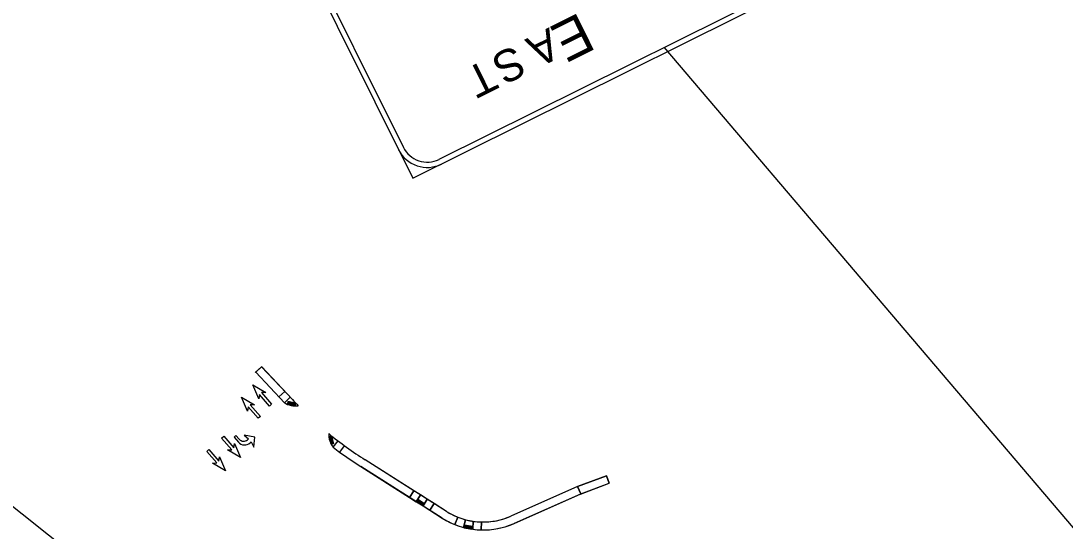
# Model space of a CAD drawing. Extents: x -5665 to 1997148, y 4 to 812485.
# Drawn here: x 1970356 to 1971011, y 803627 to 803946 of the extents above; entities that cross this region are included whole.
import ezdxf

# ---------------------------------------------------------------- set-up
doc = ezdxf.new("R2010")
doc.units = 0
for name, color, linetype in [('RD_EX_Bldg_Foundation', 7, 'Continuous'), ('RD_PD_SW', 7, 'Continuous'), ('RD_SHT_TX', 7, 'Continuous')]:
    doc.layers.add(name, color=color, linetype=linetype)

msp = doc.modelspace()

# ---------------------------------------------------------------- linework, layer by layer
at = {"layer": 'RD_EX_Bldg_Foundation'}
for p, q in [((1970505.11, 803709.66), (1970501.35, 803718.35)), ((1970501.35, 803718.35), (1970509.52, 803713.56)), ((1970498.06, 803701.97), (1970494.3, 803710.66)), ((1970494.3, 803710.66), (1970502.47, 803705.86)), ((1970505.53, 803712.27), (1970505.11, 803709.66)), ((1970511.89, 803705.08), (1970505.53, 803712.27)), ((1970509.52, 803713.56), (1970506.88, 803713.47)), ((1970506.88, 803713.47), (1970513.24, 803706.27)), ((1970498.48, 803704.58), (1970498.06, 803701.97)), ((1970504.84, 803697.39), (1970498.48, 803704.58)), ((1970502.47, 803705.86), (1970499.83, 803705.77)), ((1970499.83, 803705.77), (1970506.19, 803698.58)), ((1970513.24, 803706.27), (1970511.89, 803705.08)), ((1970506.19, 803698.58), (1970504.84, 803697.39)), ((1970481.9, 803684.94), (1970483.24, 803686.13)), ((1970488.25, 803677.74), (1970481.9, 803684.94)), ((1970483.24, 803686.13), (1970489.6, 803678.94)), ((1970490.87, 803686.65), (1970489.66, 803685.57)), ((1970490.87, 803686.65), (1970489.66, 803685.57)), ((1970489.66, 803685.57), (1970492.37, 803682.5)), ((1970489.66, 803685.57), (1970492.37, 803682.5)), ((1970492.94, 803684.3), (1970490.87, 803686.65)), ((1970490.87, 803686.65), (1970490.87, 803686.65)), ((1970492.94, 803684.3), (1970490.87, 803686.65)), ((1970490.87, 803686.65), (1970490.87, 803686.65)), ((1970502.74, 803685.51), (1970495.94, 803686.94)), ((1970495.94, 803686.94), (1970498.77, 803684.54)), ((1970502.74, 803685.51), (1970495.94, 803686.94)), ((1970495.94, 803686.94), (1970498.77, 803684.54)), ((1970498.77, 803684.54), (1970498.04, 803683.9)), ((1970498.77, 803684.54), (1970498.04, 803683.9)), ((1970502.12, 803679.28), (1970502.74, 803685.51)), ((1970502.12, 803679.28), (1970502.74, 803685.51)), ((1970472.51, 803676.64), (1970473.86, 803677.84)), ((1970478.87, 803669.45), (1970472.51, 803676.64)), ((1970473.86, 803677.84), (1970480.22, 803670.64)), ((1970485.61, 803677.65), (1970488.25, 803677.74)), ((1970493.78, 803672.86), (1970485.61, 803677.65)), ((1970489.6, 803678.94), (1970490.02, 803681.55)), ((1970490.02, 803681.55), (1970493.78, 803672.86)), ((1970499.76, 803681.96), (1970500.49, 803682.6)), ((1970499.76, 803681.96), (1970500.49, 803682.6)), ((1970500.49, 803682.6), (1970502.12, 803679.28)), ((1970500.49, 803682.6), (1970502.12, 803679.28)), ((1970480.22, 803670.64), (1970480.63, 803673.25)), ((1970480.63, 803673.25), (1970484.39, 803664.56)), ((1970476.23, 803669.36), (1970478.87, 803669.45)), ((1970484.39, 803664.56), (1970476.23, 803669.36))]:
    msp.add_line(p, q, dxfattribs=at)
for centre, radius, start, end in [((1970495.69, 803686.57), 3.56, 219.68142, 311.44424), ((1970495.69, 803686.57), 3.56, 219.68142, 311.44424), ((1970496.34, 803686), 5.29, 221.406, 310.24855), ((1970496.34, 803686), 5.29, 221.406, 310.24855)]:
    msp.add_arc(centre, radius, start, end, dxfattribs=at)
at = {"layer": 'RD_PD_SW'}
for p, q in [((1970506.97, 803729.75), (1970502.95, 803726)), ((1970506.97, 803729.75), (1970503.3, 803726.36)), ((1970506.95, 803729.78), (1970526.22, 803709.16)), ((1970526.22, 803709.16), (1970506.97, 803729.75)), ((1970503.29, 803726.36), (1970521.24, 803707.17)), ((1970503.3, 803726.36), (1970521.24, 803707.17)), ((1970517.82, 803710.82), (1970521.48, 803714.23)), ((1970521.24, 803707.17), (1970524.89, 803710.58)), ((1970551.82, 803679.24), (1970554.86, 803683.22)), ((1970555.91, 803676.19), (1970558.87, 803680.22)), ((1970622.8, 803639.13), (1970571.81, 803671.41)), ((1970602.35, 803652.07), (1970571.81, 803671.41)), ((1970620.13, 803634.9), (1970569.13, 803667.18)), ((1970569.13, 803667.18), (1970599.68, 803647.85)), ((1970704.98, 803654.59), (1970723.17, 803661.36)), ((1970723.17, 803661.36), (1970704.98, 803654.59)), ((1970706.86, 803649.96), (1970724.91, 803656.68)), ((1970707, 803650.01), (1970724.91, 803656.68)), ((1970723.17, 803661.36), (1970724.91, 803656.68)), ((1970724.91, 803656.68), (1970723.17, 803661.36)), ((1970602.35, 803652.07), (1970599.68, 803647.85)), ((1970599.68, 803647.85), (1970602.35, 803652.07)), ((1970599.68, 803647.85), (1970602.35, 803652.07)), ((1970606.58, 803649.4), (1970602.35, 803652.07)), ((1970704.98, 803654.59), (1970663.17, 803636.13)), ((1970704.98, 803654.59), (1970663.17, 803636.13)), ((1970665.19, 803631.55), (1970707, 803650.02)), ((1970706.86, 803649.96), (1970665.19, 803631.55)), ((1970707, 803650.02), (1970704.98, 803654.59)), ((1970704.98, 803654.59), (1970707, 803650.02)), ((1970599.68, 803647.85), (1970603.91, 803645.17)), ((1970603.91, 803645.17), (1970606.58, 803649.4)), ((1970606.58, 803649.4), (1970603.91, 803645.17)), ((1970603.91, 803645.17), (1970606.58, 803649.4)), ((1970603.91, 803645.17), (1970608.13, 803642.5)), ((1970610.8, 803646.72), (1970606.58, 803649.4)), ((1970610.8, 803646.72), (1970608.13, 803642.5)), ((1970608.13, 803642.5), (1970610.8, 803646.72)), ((1970608.13, 803642.5), (1970610.8, 803646.72)), ((1970615.03, 803644.05), (1970610.8, 803646.72)), ((1970612.35, 803639.82), (1970615.03, 803644.05)), ((1970615.03, 803644.05), (1970612.35, 803639.82)), ((1970612.35, 803639.82), (1970615.03, 803644.05)), ((1970622.8, 803639.13), (1970615.03, 803644.05)), ((1970608.13, 803642.5), (1970612.35, 803639.82)), ((1970612.35, 803639.82), (1970620.13, 803634.9)), ((1970628.16, 803630.82), (1970630, 803635.47)), ((1970630, 803635.47), (1970628.16, 803630.82)), ((1970628.16, 803630.82), (1970630, 803635.47)), ((1970633.52, 803629.06), (1970634.8, 803633.89)), ((1970634.8, 803633.89), (1970633.52, 803629.06)), ((1970634.8, 803633.89), (1970633.52, 803629.06)), ((1970639.39, 803627.89), (1970639.65, 803632.9)), ((1970639.65, 803632.9), (1970639.39, 803627.89)), ((1970639.65, 803632.9), (1970639.39, 803627.89)), ((1970644.61, 803627.48), (1970644.73, 803632.47)), ((1970644.73, 803632.47), (1970644.61, 803627.48)), ((1970644.61, 803627.48), (1970644.73, 803632.47))]:
    msp.add_line(p, q, dxfattribs=at)
for points in [[(1970528.29, 803706.97), (1970523.39, 803707.87), (1970523.1, 803706.29), (1970528.01, 803705.39)], [(1970550.83, 803686.33), (1970552.09, 803681.51), (1970550.55, 803681.11), (1970549.29, 803685.93)], [(1970609.02, 803643.89), (1970604.8, 803646.53), (1970603.95, 803645.18), (1970608.18, 803642.53)], [(1970639.12, 803629.55), (1970634.22, 803630.45), (1970633.93, 803628.88), (1970638.83, 803627.98)]]:
    msp.add_lwpolyline(points, close=True, dxfattribs=at)
msp.add_lwpolyline([(1970707, 803650.02), (1970707, 803650.01)], dxfattribs=at)
for centre, radius in [((1970523.45, 803706.53), 0.146), ((1970523.45, 803706.53), 0.073), ((1970523.54, 803707.02), 0.146), ((1970523.54, 803707.02), 0.073), ((1970523.64, 803707.52), 0.146), ((1970523.64, 803707.52), 0.073), ((1970523.85, 803706.46), 0.146), ((1970523.85, 803706.46), 0.073), ((1970523.94, 803706.95), 0.146), ((1970523.94, 803706.95), 0.073), ((1970524.03, 803707.45), 0.146), ((1970524.03, 803707.45), 0.073), ((1970524.24, 803706.38), 0.146), ((1970524.24, 803706.38), 0.073), ((1970524.33, 803706.87), 0.146), ((1970524.33, 803706.87), 0.073), ((1970524.42, 803707.38), 0.146), ((1970524.42, 803707.38), 0.073), ((1970524.63, 803706.31), 0.146), ((1970524.63, 803706.31), 0.073), ((1970524.72, 803706.8), 0.146), ((1970524.72, 803706.8), 0.073), ((1970524.82, 803707.3), 0.146), ((1970524.82, 803707.3), 0.073), ((1970525.03, 803706.24), 0.146), ((1970525.03, 803706.24), 0.073), ((1970525.12, 803706.73), 0.146), ((1970525.12, 803706.73), 0.073), ((1970525.21, 803707.23), 0.146), ((1970525.21, 803707.23), 0.073), ((1970525.42, 803706.17), 0.146), ((1970525.42, 803706.17), 0.073), ((1970525.51, 803706.66), 0.146), ((1970525.51, 803706.66), 0.073), ((1970525.6, 803707.16), 0.146), ((1970525.6, 803707.16), 0.073), ((1970525.81, 803706.1), 0.146), ((1970525.81, 803706.1), 0.073), ((1970525.9, 803706.59), 0.146), ((1970525.9, 803706.59), 0.073), ((1970526, 803707.09), 0.146), ((1970526, 803707.09), 0.073), ((1970526.21, 803706.02), 0.146), ((1970526.21, 803706.02), 0.073), ((1970526.3, 803706.51), 0.146), ((1970526.3, 803706.51), 0.073), ((1970526.39, 803707.01), 0.146), ((1970526.39, 803707.01), 0.073), ((1970526.6, 803705.95), 0.146), ((1970526.6, 803705.95), 0.073), ((1970526.69, 803706.44), 0.146), ((1970526.69, 803706.44), 0.073), ((1970526.78, 803706.94), 0.146), ((1970526.78, 803706.94), 0.073), ((1970527, 803705.88), 0.146), ((1970527, 803705.88), 0.073), ((1970527.09, 803706.37), 0.146), ((1970527.09, 803706.37), 0.073), ((1970527.18, 803706.87), 0.146), ((1970527.18, 803706.87), 0.073), ((1970527.39, 803705.81), 0.146), ((1970527.39, 803705.81), 0.073), ((1970527.48, 803706.3), 0.146), ((1970527.48, 803706.3), 0.073), ((1970527.57, 803706.8), 0.146), ((1970527.57, 803706.8), 0.073), ((1970527.78, 803705.73), 0.146), ((1970527.78, 803705.73), 0.073), ((1970527.87, 803706.23), 0.146), ((1970527.87, 803706.23), 0.073), ((1970527.96, 803706.73), 0.146), ((1970527.96, 803706.73), 0.073), ((1970549.64, 803685.73), 0.146), ((1970549.64, 803685.73), 0.073), ((1970549.74, 803685.34), 0.146), ((1970549.74, 803685.34), 0.073), ((1970549.84, 803684.96), 0.146), ((1970549.84, 803684.96), 0.073), ((1970549.95, 803684.57), 0.146), ((1970549.95, 803684.57), 0.073), ((1970550.05, 803684.18), 0.146), ((1970550.05, 803684.18), 0.073), ((1970550.13, 803685.86), 0.146), ((1970550.15, 803683.8), 0.146), ((1970550.13, 803685.86), 0.073), ((1970550.23, 803685.47), 0.146), ((1970550.15, 803683.8), 0.073), ((1970550.25, 803683.41), 0.146), ((1970550.23, 803685.47), 0.073), ((1970550.33, 803685.08), 0.146), ((1970550.25, 803683.41), 0.073), ((1970550.35, 803683.02), 0.146), ((1970550.33, 803685.08), 0.073), ((1970550.43, 803684.7), 0.146), ((1970550.35, 803683.02), 0.073), ((1970550.45, 803682.64), 0.146), ((1970550.43, 803684.7), 0.073), ((1970550.53, 803684.31), 0.146), ((1970550.45, 803682.64), 0.073), ((1970550.53, 803684.31), 0.073), ((1970550.62, 803685.99), 0.146), ((1970550.63, 803683.92), 0.146), ((1970550.62, 803685.99), 0.073), ((1970550.63, 803683.92), 0.073), ((1970550.72, 803685.6), 0.146), ((1970550.73, 803683.54), 0.146), ((1970550.72, 803685.6), 0.073), ((1970550.73, 803683.54), 0.073), ((1970550.82, 803685.21), 0.146), ((1970550.83, 803683.15), 0.146), ((1970550.82, 803685.21), 0.073), ((1970550.83, 803683.15), 0.073), ((1970550.92, 803684.83), 0.146), ((1970550.93, 803682.76), 0.146), ((1970550.92, 803684.83), 0.073), ((1970550.93, 803682.76), 0.073), ((1970551.02, 803684.44), 0.146), ((1970551.02, 803684.44), 0.073), ((1970551.12, 803684.05), 0.146), ((1970551.12, 803684.05), 0.073), ((1970551.22, 803683.66), 0.146), ((1970551.22, 803683.66), 0.073), ((1970551.33, 803683.28), 0.146), ((1970551.33, 803683.28), 0.073), ((1970551.43, 803682.89), 0.146), ((1970551.43, 803682.89), 0.073), ((1970551.53, 803682.5), 0.146), ((1970550.55, 803682.25), 0.146), ((1970550.55, 803682.25), 0.073), ((1970550.65, 803681.86), 0.146), ((1970550.65, 803681.86), 0.073), ((1970550.76, 803681.47), 0.146), ((1970550.76, 803681.47), 0.073), ((1970551.04, 803682.37), 0.146), ((1970551.04, 803682.37), 0.073), ((1970551.14, 803681.99), 0.146), ((1970551.14, 803681.99), 0.073), ((1970551.24, 803681.6), 0.146), ((1970551.24, 803681.6), 0.073), ((1970551.53, 803682.5), 0.073), ((1970551.63, 803682.12), 0.146), ((1970551.63, 803682.12), 0.073), ((1970551.73, 803681.73), 0.146), ((1970551.73, 803681.73), 0.073), ((1970604.36, 803645.27), 0.146), ((1970604.36, 803645.27), 0.073), ((1970604.63, 803645.69), 0.146), ((1970604.63, 803645.69), 0.073), ((1970604.7, 803645.05), 0.146), ((1970604.7, 803645.05), 0.073), ((1970604.9, 803646.12), 0.146), ((1970604.9, 803646.12), 0.073), ((1970604.97, 803645.48), 0.146), ((1970604.97, 803645.48), 0.073), ((1970605.04, 803644.84), 0.146), ((1970605.04, 803644.84), 0.073), ((1970605.24, 803645.91), 0.146), ((1970605.24, 803645.91), 0.073), ((1970605.3, 803645.26), 0.146), ((1970605.3, 803645.26), 0.073), ((1970605.38, 803644.63), 0.146), ((1970605.38, 803644.63), 0.073), ((1970605.57, 803645.7), 0.146), ((1970605.57, 803645.7), 0.073), ((1970605.64, 803645.05), 0.146), ((1970605.64, 803645.05), 0.073), ((1970605.72, 803644.42), 0.146), ((1970605.72, 803644.42), 0.073), ((1970605.91, 803645.48), 0.146), ((1970605.91, 803645.48), 0.073), ((1970605.98, 803644.84), 0.146), ((1970605.98, 803644.84), 0.073), ((1970606.06, 803644.21), 0.146), ((1970606.06, 803644.21), 0.073), ((1970606.25, 803645.27), 0.146), ((1970606.25, 803645.27), 0.073), ((1970606.32, 803644.63), 0.146), ((1970606.32, 803644.63), 0.073), ((1970606.4, 803643.99), 0.146), ((1970606.4, 803643.99), 0.073), ((1970606.59, 803645.06), 0.146), ((1970606.59, 803645.06), 0.073), ((1970606.66, 803644.42), 0.146), ((1970606.66, 803644.42), 0.073), ((1970606.74, 803643.78), 0.146), ((1970606.74, 803643.78), 0.073), ((1970606.93, 803644.85), 0.146), ((1970606.93, 803644.85), 0.073), ((1970607, 803644.2), 0.146), ((1970607, 803644.2), 0.073), ((1970607.08, 803643.57), 0.146), ((1970607.08, 803643.57), 0.073), ((1970607.27, 803644.64), 0.146), ((1970607.34, 803643.99), 0.146), ((1970607.27, 803644.64), 0.073), ((1970607.34, 803643.99), 0.073), ((1970607.42, 803643.36), 0.146), ((1970607.42, 803643.36), 0.073), ((1970607.61, 803644.42), 0.146), ((1970607.68, 803643.78), 0.146), ((1970607.61, 803644.42), 0.073), ((1970607.68, 803643.78), 0.073), ((1970607.95, 803644.21), 0.146), ((1970608.02, 803643.57), 0.146), ((1970607.95, 803644.21), 0.073), ((1970608.02, 803643.57), 0.073), ((1970608.29, 803644), 0.146), ((1970608.36, 803643.36), 0.146), ((1970608.29, 803644), 0.073), ((1970608.36, 803643.36), 0.073), ((1970608.63, 803643.79), 0.146), ((1970608.63, 803643.79), 0.073), ((1970607.75, 803643.15), 0.146), ((1970607.75, 803643.15), 0.073), ((1970608.09, 803642.93), 0.146), ((1970608.09, 803642.93), 0.073), ((1970634.46, 803630.11), 0.146), ((1970634.28, 803629.11), 0.146), ((1970634.28, 803629.11), 0.073), ((1970634.37, 803629.6), 0.146), ((1970634.37, 803629.6), 0.073), ((1970634.46, 803630.11), 0.073), ((1970634.68, 803629.04), 0.146), ((1970634.68, 803629.04), 0.073), ((1970634.77, 803629.53), 0.146), ((1970634.77, 803629.53), 0.073), ((1970634.86, 803630.03), 0.146), ((1970634.86, 803630.03), 0.073), ((1970635.07, 803628.97), 0.146), ((1970635.07, 803628.97), 0.073), ((1970635.16, 803629.46), 0.146), ((1970635.16, 803629.46), 0.073), ((1970635.25, 803629.96), 0.146), ((1970635.25, 803629.96), 0.073), ((1970635.46, 803628.9), 0.146), ((1970635.46, 803628.9), 0.073), ((1970635.55, 803629.39), 0.146), ((1970635.55, 803629.39), 0.073), ((1970635.64, 803629.89), 0.146), ((1970635.64, 803629.89), 0.073), ((1970635.86, 803628.83), 0.146), ((1970635.86, 803628.83), 0.073), ((1970635.95, 803629.32), 0.146), ((1970635.95, 803629.32), 0.073), ((1970636.04, 803629.82), 0.146), ((1970636.04, 803629.82), 0.073), ((1970636.25, 803628.75), 0.146), ((1970636.25, 803628.75), 0.073), ((1970636.34, 803629.24), 0.146), ((1970636.34, 803629.24), 0.073), ((1970636.43, 803629.74), 0.146), ((1970636.43, 803629.74), 0.073), ((1970636.64, 803628.68), 0.146), ((1970636.64, 803628.68), 0.073), ((1970636.73, 803629.17), 0.146), ((1970636.73, 803629.17), 0.073), ((1970636.82, 803629.67), 0.146), ((1970636.82, 803629.67), 0.073), ((1970637.04, 803628.61), 0.146), ((1970637.04, 803628.61), 0.073), ((1970637.13, 803629.1), 0.146), ((1970637.13, 803629.1), 0.073), ((1970637.22, 803629.6), 0.146), ((1970637.22, 803629.6), 0.073), ((1970637.43, 803628.54), 0.146), ((1970637.43, 803628.54), 0.073), ((1970637.52, 803629.03), 0.146), ((1970637.52, 803629.03), 0.073), ((1970637.61, 803629.53), 0.146), ((1970637.61, 803629.53), 0.073), ((1970637.82, 803628.46), 0.146), ((1970637.82, 803628.46), 0.073), ((1970637.91, 803628.96), 0.146), ((1970637.91, 803628.96), 0.073), ((1970638.01, 803629.46), 0.146), ((1970638.01, 803629.46), 0.073), ((1970638.22, 803628.39), 0.146), ((1970638.22, 803628.39), 0.073), ((1970638.31, 803628.88), 0.146), ((1970638.31, 803628.88), 0.073), ((1970638.4, 803629.38), 0.146), ((1970638.4, 803629.38), 0.073), ((1970638.61, 803628.32), 0.146), ((1970638.61, 803628.32), 0.073), ((1970638.7, 803628.81), 0.146), ((1970638.7, 803628.81), 0.073), ((1970638.79, 803629.31), 0.146), ((1970638.79, 803629.31), 0.073)]:
    msp.add_circle(centre, radius, dxfattribs=at)
for centre, radius, start, end in [((1970696.42, 803868.28), 233, 223.07209, 224.38413), ((1970696.42, 803868.28), 233, 223.07209, 224.38413), ((1970528.25, 803718.7), 13.5, 238.71456, 277.0521), ((1970696.42, 803868.28), 233, 230.76603, 237.667), ((1970696.42, 803868.28), 233, 230.76603, 237.667), ((1970562.55, 803687.44), 13.5, 178.45606, 217.38801), ((1970696.42, 803868.28), 238, 232.58617, 237.667), ((1970696.42, 803868.28), 238, 232.58617, 237.667), ((1970645.8, 803675.46), 43, 237.667, 248.43811), ((1970645.8, 803675.46), 43, 237.667, 293.832), ((1970645.8, 803675.46), 48, 237.667, 248.43811), ((1970645.8, 803675.46), 48, 237.667, 293.832), ((1970645.8, 803675.46), 48, 248.43811, 255.17736), ((1970645.8, 803675.46), 43, 248.43811, 255.17736), ((1970645.8, 803675.46), 43, 255.17736, 261.77452), ((1970645.8, 803675.46), 43, 261.77452, 268.57479), ((1970645.8, 803675.46), 48, 268.57479, 293.832), ((1970645.8, 803675.46), 43, 268.57479, 293.832), ((1970645.8, 803675.46), 48, 255.17736, 262.32466), ((1970645.8, 803675.46), 48, 262.32466, 268.57479)]:
    msp.add_arc(centre, radius, start, end, dxfattribs=at)
at = {"layer": 'RD_SHT_TX'}
for p, q in [((1970944.17, 803171.9), (1969902.74, 803997.33)), ((1971839.58, 802661.72), (1970759.35, 803929.81))]:
    msp.add_line(p, q, dxfattribs=at)
for points in [[(1970530.51, 803991), (1970601.74, 803847.73), (1970906.19, 803999.1), (1970834.96, 804142.37), (1970834.96, 804142.37), (1970834.96, 804142.37)], [(1970533.5, 803992.49), (1970595.82, 803867.12)], [(1970618.17, 803859.62), (1970886.8, 803993.18)], [(1970618.17, 803859.62), (1970618.17, 803859.62), (1970618.17, 803859.62)]]:
    msp.add_lwpolyline(points, dxfattribs=at)
for radius in [16.67, 20]:
    msp.add_arc((1970610.75, 803874.54), radius, 206.43534, 296.43555, dxfattribs=at)

# ---------------------------------------------------------------- texts
for s, height, p in [('E', 25, (1970706.47, 803951.92)), ('A', 20, (1970687.27, 803942.37)), ('S', 20, (1970665.67, 803931.63)), ('T', 20, (1970647.7, 803922.7))]:
    msp.add_text(s, height=height, rotation=206.43534, dxfattribs=at).set_placement(p)

doc.saveas('drawing.dxf')
